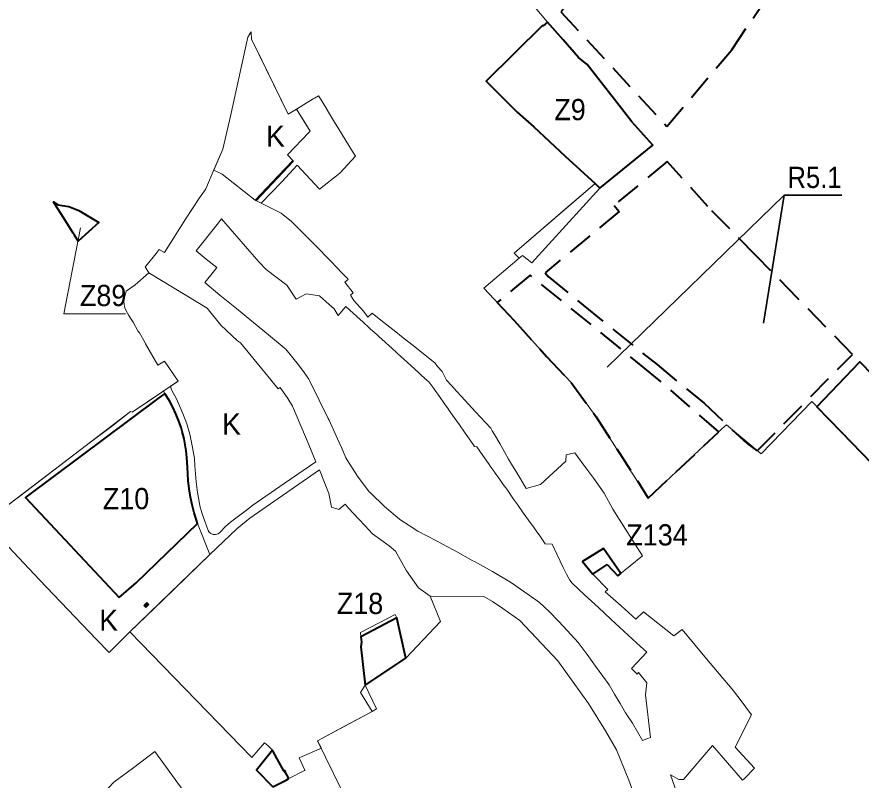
# Model space of a CAD drawing. Extents: x -650276 to -642489, y -1074425 to -1066658.
# Drawn here: x -646722 to -645767, y -1072612 to -1071749 of the extents above; entities that cross this region are included whole.
import ezdxf

# ---------------------------------------------------------------- set-up
doc = ezdxf.new("R2010")
doc.units = 0
doc.header["$LTSCALE"] = 9.6
doc.linetypes.add('MEDIUM_DASHED', pattern=[4.5, 3, -1.5])
for name, color, linetype, lineweight in [('1', 7, 'Continuous', 13), ('4', 7, 'Continuous', 40), ('43', 7, 'Continuous', 13), ('44', 7, 'Continuous', 40), ('45', 7, 'Continuous', 40), ('46', 7, 'Continuous', 13), ('47', 7, 'Continuous', 13), ('61', 7, 'MEDIUM_DASHED', 40), ('62', 7, 'Continuous', 35)]:
    doc.layers.add(name, color=color, linetype=linetype, lineweight=lineweight)

msp = doc.modelspace()

# ---------------------------------------------------------------- hatches: boundary and pattern name
at = {"layer": '1'}
msp.add_hatch(color=256, dxfattribs=at).paths.add_polyline_path([(-646578.73, -1072414.85), (-646576.66, -1072416.99), (-646573.22, -1072413.66), (-646575.31, -1072411.52)])

# ---------------------------------------------------------------- linework, layer by layer
for points in [[(-646154, -1072022), (-646160, -1072016), (-646156.858, -1072013.393), (-646068.317, -1071937.555), (-646102.04, -1071906.4), (-646137.74, -1071873.31), (-646156.59, -1071856.53), (-646174.69, -1071838.69), (-646191.57, -1071821.44), (-646136.12, -1071767.07), (-646127.84, -1071758.53), (-646127.12, -1071759.15), (-646122.16, -1071754.78), (-646136.17, -1071738.31)], [(-646565.01, -1072016.41), (-646561.43, -1072012.01), (-646555.52, -1072015.55), (-646531.63, -1071977.65), (-646515.67, -1071953.6), (-646510.36, -1071945.61), (-646508.83, -1071943.3), (-646498.33, -1071919.22), (-646489.34, -1071898.61), (-646480.81, -1071861.18), (-646461.09, -1071771.76), (-646459.66, -1071769.15), (-646457.52, -1071765.98), (-646456.96, -1071774.2), (-646415.46, -1071859.05), (-646405.99, -1071853.26), (-646387.17, -1071841.76), (-646385.73, -1071840.88), (-646381.21, -1071838.12), (-646378.15, -1071842.85), (-646363.05, -1071867.91), (-646358.29, -1071875.79), (-646342.76, -1071901.21), (-646339.33, -1071906.58), (-646357.09, -1071925.59), (-646380.09, -1071943.87), (-646405.32, -1071916.59), (-646422.82, -1071935.5), (-646446.22, -1071959.67), (-646423.62, -1071970.84), (-646411.66, -1071980.54), (-646397.04, -1071994.94), (-646382.64, -1072009.55), (-646369.88, -1072022.49), (-646367.74, -1072024.72), (-646360.53, -1072032.22), (-646354.71, -1072038.28), (-646348.89, -1072044.34), (-646347.47, -1072045.83), (-646349.03, -1072047.09), (-646351.45, -1072049.03), (-646342.13, -1072060.94), (-646344.94, -1072063.53), (-646341.21, -1072069.74), (-646337.87, -1072073.42), (-646330.33, -1072081.74), (-646325.21, -1072088.45), (-646320.51, -1072084.13), (-646312.51, -1072090.43), (-646307.16, -1072094.67), (-646300.49, -1072099.96), (-646293.83, -1072105.24), (-646287.16, -1072110.52), (-646272.37, -1072122.25), (-646249.36, -1072140.5), (-646246.39, -1072144.56), (-646241.37, -1072150.02), (-646236.35, -1072159.85), (-646230.66, -1072166.02), (-646224.96, -1072172.2), (-646219.27, -1072178.37), (-646211.37, -1072186.94), (-646203.48, -1072195.51), (-646197.78, -1072201.68), (-646192.09, -1072207.86), (-646186.39, -1072214.03), (-646184.57, -1072217.04), (-646182.05, -1072221.45), (-646176.21, -1072231.64), (-646170.37, -1072241.84), (-646166.08, -1072249.31), (-646161.69, -1072256.68), (-646157.3, -1072264.05), (-646152.81, -1072271.52), (-646148.45, -1072278.73), (-646146.27, -1072282.34), (-646130.2, -1072277.79), (-646101.53, -1072251.45), (-646101.18, -1072244.23), (-646091.27, -1072242.07), (-646081.08, -1072256.01), (-646069.73, -1072270.99), (-646057.93, -1072287.58), (-646048.32, -1072305.81), (-646026.55, -1072339.67), (-646014.64, -1072358.74), (-646042.65, -1072381.23), (-646054.43, -1072368.34), (-646071, -1072379.27), (-646053.82, -1072396.53), (-646056.71, -1072399.15), (-646038.76, -1072415.27), (-646022.31, -1072430.03), (-646013.49, -1072421.84)], [(-646381.21, -1071838.12), (-646385.73, -1071840.88), (-646387.17, -1071841.76), (-646405.99, -1071853.26), (-646399.72, -1071863.5)], [(-646380.09, -1071943.87), (-646357.09, -1071925.59), (-646339.33, -1071906.58), (-646342.76, -1071901.21), (-646358.29, -1071875.79), (-646363.05, -1071867.91), (-646378.15, -1071842.85), (-646381.21, -1071838.12)], [(-646399.72, -1071863.5), (-646390.732, -1071878.171), (-646391.83, -1071879.32), (-646416.2, -1071904.81), (-646410.25, -1071911.25), (-646426.84, -1071928.72), (-646453.04, -1071956.3), (-646446.22, -1071959.67)], [(-646446.22, -1071959.67), (-646422.82, -1071935.5), (-646405.32, -1071916.59), (-646380.09, -1071943.87)], [(-646068.317, -1071937.555), (-646099.073, -1071963.899), (-646156.858, -1072013.393)], [(-646154, -1072022), (-646150.226, -1072018.826), (-646139.98, -1072027.22), (-646062.91, -1071942.55), (-646068.317, -1071937.555)], [(-646009.81, -1072467.72), (-646021.04, -1072457.32), (-646035.81, -1072443.64), (-646050.33, -1072430.19), (-646064.38, -1072417.18), (-646080.11, -1072402.61), (-646094.3, -1072389.47), (-646096.74, -1072386.1), (-646100.79, -1072379.38), (-646104.34, -1072371.88), (-646111.23, -1072357.28), (-646116.89, -1072345.3), (-646124.57, -1072345.05), (-646130.92, -1072336.06), (-646135.06, -1072330.21), (-646137.35, -1072326.93), (-646143.44, -1072318.35), (-646149.48, -1072309.81), (-646156.16, -1072300.36), (-646160.44, -1072294.29), (-646162.83, -1072290.91), (-646167.16, -1072284.79), (-646169.4, -1072281.62), (-646172.17, -1072277.7), (-646175.95, -1072272.36), (-646177.05, -1072270.8), (-646181.94, -1072263.89), (-646182.5, -1072263.09), (-646186.83, -1072256.95), (-646188.78, -1072254.2), (-646193.5, -1072247.52), (-646195.15, -1072245.18), (-646202.08, -1072235.38), (-646204.52, -1072235.01), (-646210.34, -1072226.72), (-646216.04, -1072218.6), (-646221.81, -1072210.37), (-646227.62, -1072202.1), (-646233.19, -1072194.16), (-646234.49, -1072192.31), (-646238.48, -1072186.62), (-646239.32, -1072185.42), (-646243.62, -1072179.29), (-646244.21, -1072178.45), (-646249.07, -1072171.52), (-646250.54, -1072169.43), (-646253.99, -1072164.89), (-646256.42, -1072161.7), (-646258.35, -1072160.04), (-646264.53, -1072154.43), (-646267.64, -1072151.6), (-646276.92, -1072143.18), (-646284.31, -1072136.47), (-646291.65, -1072129.81), (-646299.17, -1072122.98), (-646300.37, -1072121.89), (-646306.22, -1072116.58), (-646312.43, -1072110.94), (-646313.68, -1072109.81), (-646318.69, -1072105.26), (-646321.85, -1072102.39), (-646324.94, -1072099.59), (-646329.95, -1072095.03), (-646331.17, -1072093.93), (-646337.42, -1072088.25), (-646338.2, -1072087.54), (-646345.68, -1072080.75), (-646350.2, -1072076.65), (-646358.85, -1072086.64), (-646363.59, -1072079.32), (-646369.14, -1072074.36), (-646380.25, -1072064.44), (-646395.21, -1072062.3), (-646406.46, -1072068.39), (-646417.04, -1072052.27), (-646440.49, -1072034.75), (-646448.23, -1072026.42), (-646458.91, -1072014.27), (-646490.776, -1071977.349), (-646495.86, -1071983.75), (-646519.64, -1072013.69)], [(-646595.86, -1072086.82), (-646598.67, -1072081.55), (-646600.22, -1072077.86), (-646600.8, -1072075.94), (-646601.16, -1072074.07), (-646601.42, -1072071.01), (-646601, -1072067.55), (-646599.86, -1072063.71), (-646598.827, -1072059.244), (-646588.75, -1072052.06), (-646573.05, -1072038.46), (-646577.31, -1072031.53), (-646576.72, -1072030.81), (-646565.01, -1072016.41)], [(-646519.64, -1072013.69), (-646508.3, -1072022.8), (-646496.18, -1072032.53), (-646502.89, -1072040.91), (-646509.76, -1072049.5), (-646492.67, -1072063.57), (-646490.82, -1072065.09), (-646473.97, -1072078.95), (-646456.63, -1072093.22), (-646454.82, -1072094.71), (-646437.75, -1072108.75), (-646420.06, -1072123.31), (-646418.13, -1072124.9), (-646403.75, -1072142.38), (-646397.31, -1072151.31), (-646392.06, -1072158.59), (-646391.02, -1072161.06), (-646380.5, -1072182.54), (-646370.34, -1072203.29), (-646369.17, -1072205.2), (-646359.65, -1072226.35), (-646354.89, -1072236.93), (-646350.13, -1072247.52), (-646349.03, -1072249.42), (-646337.06, -1072268.4)], [(-646156.858, -1072013.393), (-646160, -1072016), (-646154, -1072022)], [(-646008.07, -1072293.223), (-646067.08, -1072201.18), (-646095.44, -1072162.47), (-646123.06, -1072133.18), (-646159.66, -1072092.31), (-646194.191, -1072055.797), (-646154, -1072022)], [(-646577.08, -1072118.7), (-646577.41, -1072117.76), (-646583.9, -1072106.42), (-646585.08, -1072104.81), (-646591.02, -1072094.4), (-646593.13, -1072091.01), (-646595.86, -1072086.82)], [(-646737.449, -1072305.019), (-646643.55, -1072233.5), (-646593.85, -1072195.48), (-646592.2, -1072196.17), (-646539.94, -1072160.83), (-646555.49, -1072138.17), (-646563.11, -1072143.03), (-646577.08, -1072118.7)], [(-645674, -1072338), (-645823, -1072184), (-645880.412, -1072243.358), (-645919.698, -1072210.262), (-645924.734, -1072214.99), (-646008.065, -1072293.22)], [(-646293.93, -1072353.28), (-646301.43, -1072347.28), (-646320.28, -1072333.64), (-646328.57, -1072324.62), (-646335.52, -1072317.05), (-646347.2, -1072304.53), (-646351.15, -1072300), (-646358.28, -1072306.16), (-646366.62, -1072303.53), (-646369.35, -1072287.95), (-646380.12, -1072261.44), (-646459.03, -1072316.137), (-646473.069, -1072327.765), (-646504.244, -1072357.026), (-646557.188, -1072408.65), (-646594.561, -1072444.38), (-646456.592, -1072586.826)], [(-646337.06, -1072268.4), (-646323.76, -1072286.05), (-646322.37, -1072287.43), (-646306.56, -1072302.91), (-646289.72, -1072317.17), (-646287.88, -1072318.32), (-646278.46, -1072324.39), (-646268.81, -1072330.59), (-646248.36, -1072341.06), (-646246.79, -1072341.94), (-646236.62, -1072347.54), (-646226.6, -1072353.06), (-646206.45, -1072364.17), (-646204.61, -1072365.07), (-646184.28, -1072376.27), (-646164.58, -1072387.87), (-646162.91, -1072388.99), (-646152.72, -1072396.2), (-646142.81, -1072403.2), (-646131.25, -1072411.38), (-646120.15, -1072421.49), (-646109.85, -1072432.52), (-646099.59, -1072443.5), (-646087.36, -1072456.59), (-646077.32, -1072470.36), (-646067.89, -1072483.29), (-646059.6, -1072494.67), (-646052.46, -1072504.47), (-646046.19, -1072515.07), (-646040.06, -1072525.44), (-646033.79, -1072536.03), (-646025.88, -1072547.72), (-646014.58, -1072567.38), (-646009.73, -1072565.6), (-646005.7, -1072564.121), (-646011.28, -1072515.68), (-646009.61, -1072502.32), (-646018.97, -1072490.66), (-646020.51, -1072492.32), (-646027.04, -1072485.99), (-646009.81, -1072467.72)], [(-646433.36, -1072578.45), (-646432.57, -1072579.75), (-646427.95, -1072588.07), (-646420.36, -1072601.78), (-646419.02, -1072604.18), (-646419.47, -1072601.31), (-646419.11, -1072602.03), (-646414.77, -1072610.61), (-646397.18, -1072601.51), (-646396.49, -1072601.15), (-646403.01, -1072587.22), (-646402.24, -1072586.89), (-646377.84, -1072576.29), (-646382.41, -1072568.01), (-646320.62, -1072534.6), (-646333.56, -1072513.13), (-646328.45, -1072504.81), (-646333.34, -1072461.67), (-646332.68, -1072456.19), (-646333.33, -1072450.12), (-646333.84, -1072445.32), (-646332.82, -1072444.79), (-646294.51, -1072424.9), (-646292.44, -1072428.89), (-646282.47, -1072474.34), (-646243.17, -1072432.88), (-646254.75, -1072404.25), (-646268.05, -1072394.66), (-646281.83, -1072375.54), (-646293.93, -1072353.28)], [(-646013.49, -1072421.84), (-645979.11, -1072449.23), (-645969.88, -1072441.74), (-645955.1, -1072459.76), (-645944.25, -1072472.98), (-645927.82, -1072492.14)], [(-645927.82, -1072492.14), (-645913.04, -1072509.37), (-645904.25, -1072521.2), (-645891.33, -1072538.6), (-645909.952, -1072574.829), (-645888.07, -1072598.68), (-645899.69, -1072610.7), (-645901.33, -1072612.4), (-645935.38, -1072573), (-645968.24, -1072611.54), (-645973.45, -1072611.73), (-645982.84, -1072606.46), (-645955.51, -1072684.762)], [(-646456.592, -1072586.826), (-646442.31, -1072569.97), (-646438.05, -1072573.49), (-646433.36, -1072578.45)], [(-646524.818, -1072657.852), (-646517.19, -1072650.7), (-646511.84, -1072645.84), (-646510.28, -1072644.42), (-646531.13, -1072626.73), (-646534.36, -1072624), (-646566.49, -1072579.96), (-646591.49, -1072599.19), (-646612.66, -1072614.57), (-646618.94, -1072620.88), (-646629.86, -1072632.07), (-646627.32, -1072636.95), (-646605.23, -1072679.37), (-646589.37, -1072709.83)]]:
    msp.add_lwpolyline(points, dxfattribs=at)
msp.add_lwpolyline([(-646578.73, -1072414.85), (-646576.66, -1072416.99), (-646573.22, -1072413.66), (-646575.31, -1072411.52)], close=True, dxfattribs=at)
at = {"layer": '4'}
for points in [[(-646039.16, -1072378.43), (-646058.64, -1072350.29), (-646082.55, -1072364.84), (-646071, -1072379.27), (-646054.43, -1072368.34)], [(-646054.43, -1072368.34), (-646042.65, -1072381.23), (-646039.16, -1072378.43)]]:
    msp.add_lwpolyline(points, dxfattribs=at)
at = {"layer": '44'}
msp.add_lwpolyline([(-646652.18, -1071967.73), (-646629.655, -1071981.343), (-646653.198, -1072002.544), (-646657.32, -1071995.98), (-646658.79, -1071993.62), (-646669.31, -1071976.77), (-646676.79, -1071964.97), (-646681.07, -1071958.16), (-646675.99, -1071961.64), (-646663.87, -1071963.26)], close=True, dxfattribs=at)
at = {"layer": '44', "lineweight": 13}
msp.add_lwpolyline([(-646599.686, -1072084.891), (-646669.193, -1072084.891), (-646650.508, -1071987.658)], dxfattribs=at)
msp.add_lwpolyline([(-646599.686, -1072084.891), (-646669.193, -1072084.891), (-646650.508, -1071987.658)], dxfattribs=at)
at = {"layer": '45'}
msp.add_line((-646417.787, -1072612.168), (-646414.77, -1072610.61), dxfattribs=at)
for points in [[(-646102.04, -1071906.4), (-646068.317, -1071937.555), (-646062.91, -1071942.55), (-646002.93, -1071893.984), (-646026.64, -1071867.44), (-646043.49, -1071845.87), (-646077.32, -1071802.59), (-646087, -1071795), (-646104.5, -1071774.86), (-646122.16, -1071754.78), (-646127.12, -1071759.15), (-646127.84, -1071758.53), (-646191.57, -1071821.44), (-646174.69, -1071838.69), (-646156.59, -1071856.53), (-646137.74, -1071873.31)], [(-645817.219, -1072189.975), (-645768.649, -1072139.283), (-645740.45, -1072168.23), (-645559.34, -1072354.42), (-645546.82, -1072365.72), (-645550.41, -1072368.47), (-645636.37, -1072379.57), (-645650.78, -1072342.73), (-645674, -1072338), (-645789.298, -1072218.833)], [(-646606.848, -1072405.785), (-646587.666, -1072389.082), (-646518.208, -1072321.92), (-646519.417, -1072318.408), (-646522.007, -1072309.932), (-646524.282, -1072300.849), (-646526, -1072292.201), (-646527.5, -1072282.657), (-646528.566, -1072273.308), (-646529.182, -1072265.941), (-646529.607, -1072258.124), (-646530.188, -1072247.442), (-646530.892, -1072239.747), (-646531.93, -1072232.861), (-646533.286, -1072226.031), (-646535.344, -1072217.844), (-646536.772, -1072213.218), (-646539.168, -1072206.122), (-646539.168, -1072206.122), (-646542.484, -1072197.985), (-646546.09, -1072190.428), (-646549.793, -1072183.38), (-646554.56, -1072175.629), (-646555.051, -1072174.933), (-646563.299, -1072181.091), (-646710.684, -1072291.133), (-646712.634, -1072292.59)], [(-646333.34, -1072461.67), (-646328.45, -1072504.81), (-646282.47, -1072474.34), (-646292.44, -1072428.89), (-646333.33, -1072450.12), (-646332.68, -1072456.19)], [(-646333.34, -1072461.67), (-646328.45, -1072504.81), (-646282.47, -1072474.34), (-646292.44, -1072428.89), (-646333.33, -1072450.12), (-646332.68, -1072456.19)]]:
    msp.add_lwpolyline(points, close=True, dxfattribs=at)
for points in [[(-646420.36, -1072601.78), (-646427.95, -1072588.07), (-646432.57, -1072579.75), (-646433.36, -1072578.45), (-646451.458, -1072601.008), (-646433.024, -1072620.04), (-646417.787, -1072612.168)], [(-646414.77, -1072610.61), (-646419.11, -1072602.03), (-646419.47, -1072601.31), (-646419.02, -1072604.18), (-646420.36, -1072601.78)]]:
    msp.add_lwpolyline(points, dxfattribs=at)
at = {"layer": '47'}
msp.add_line((-646490.111, -1071926.754), (-646453.04, -1071956.3), dxfattribs=at)
for points in [[(-646453.04, -1071956.3), (-646451.87, -1071956.88), (-646409.4, -1071912.17), (-646416.2, -1071904.81), (-646391.83, -1071879.32), (-646390.732, -1071878.171), (-646405.99, -1071853.26), (-646415.46, -1071859.05), (-646445.115, -1071798.418), (-646456.96, -1071774.2), (-646457.52, -1071765.98), (-646461.09, -1071771.76), (-646480.81, -1071861.18), (-646489.34, -1071898.61), (-646499.741, -1071922.455), (-646490.111, -1071926.754)], [(-646507.28, -1072078.4), (-646530.073, -1072064.559), (-646573.05, -1072038.46), (-646588.75, -1072052.06), (-646598.827, -1072059.244), (-646599.86, -1072063.71), (-646601, -1072067.55), (-646601.42, -1072071.01), (-646601.16, -1072074.07), (-646600.8, -1072075.94), (-646600.22, -1072077.86), (-646598.67, -1072081.55), (-646595.86, -1072086.82), (-646593.13, -1072091.01), (-646591.02, -1072094.4), (-646585.08, -1072104.81), (-646583.9, -1072106.42), (-646577.41, -1072117.76), (-646577.08, -1072118.7), (-646563.11, -1072143.03), (-646555.49, -1072138.17), (-646539.94, -1072160.83), (-646548.676, -1072166.737)], [(-646472.72, -1072115.38), (-646491.69, -1072097.45), (-646507.28, -1072078.4)], [(-646426.98, -1072169.74), (-646441.961, -1072151.281), (-646469.41, -1072117.44), (-646472.72, -1072115.38)], [(-646548.676, -1072166.737), (-646547.606, -1072170.835), (-646541.822, -1072181.102), (-646534.527, -1072197.411), (-646530.167, -1072209.31), (-646526.798, -1072221.011), (-646523.628, -1072235.883)], [(-646415.84, -1072180.43), (-646424.56, -1072167.96), (-646426.98, -1072169.74)], [(-646731.82, -1072348.2), (-646696.83, -1072385.81), (-646632.356, -1072453.247), (-646618.158, -1072468.098), (-646611.091, -1072460.994), (-646594.606, -1072444.422), (-646594.561, -1072444.38), (-646504.244, -1072357.026), (-646518.208, -1072321.92), (-646587.666, -1072389.082), (-646606.848, -1072405.785), (-646712.634, -1072292.59), (-646563.299, -1072181.091), (-646556.591, -1072176.083), (-646555.051, -1072174.933), (-646556.693, -1072172.16), (-646568.051, -1072179.84), (-646592.2, -1072196.17), (-646593.85, -1072195.48), (-646614.075, -1072210.952), (-646643.55, -1072233.5), (-646693.58, -1072271.606), (-646716.167, -1072288.809), (-646737.449, -1072305.019)], [(-646391.77, -1072233.91), (-646410.68, -1072189.36), (-646415.84, -1072180.43)], [(-646523.628, -1072235.883), (-646523.628, -1072235.883), (-646521.646, -1072248.378), (-646521.051, -1072256.707), (-646519.756, -1072274.861), (-646518.079, -1072287.051), (-646516.692, -1072294.983), (-646515.305, -1072301.925), (-646512.729, -1072311.048), (-646509.954, -1072319.377), (-646506.189, -1072329.889), (-646504.802, -1072331.971), (-646503.018, -1072333.459), (-646500.244, -1072334.45), (-646497.569, -1072334.55), (-646494.794, -1072333.558), (-646492.813, -1072332.07), (-646486.273, -1072325.526), (-646480.923, -1072320.667), (-646462.79, -1072306.784), (-646455.557, -1072301.131), (-646420.085, -1072276.737), (-646384.056, -1072252.138), (-646391.77, -1072233.91)], [(-645999.622, -1072714.927), (-646006.66, -1072681.4), (-646019.16, -1072642.35), (-646030.17, -1072612.31), (-646043.87, -1072578.12), (-646056.42, -1072556.49), (-646075.82, -1072525.54), (-646110.61, -1072477.49), (-646153.49, -1072431.54), (-646172.81, -1072418.2), (-646184.449, -1072410.256), (-646194.19, -1072404.62), (-646254.75, -1072404.25), (-646243.17, -1072432.88), (-646282.47, -1072474.34), (-646328.45, -1072504.81), (-646315.452, -1072531.573)], [(-646315.452, -1072531.573), (-646320.62, -1072534.6), (-646350.18, -1072550.59), (-646382.41, -1072568.01), (-646345.6, -1072642.55), (-646368.51, -1072652.81), (-646371.66, -1072654.2), (-646342.08, -1072717.43), (-646367.72, -1072730.68), (-646321.171, -1072780.535), (-646292.17, -1072811.6), (-646261.97, -1072849.66), (-646255.39, -1072850.83), (-646249.04, -1072847.16), (-646253.56, -1072838.8), (-646288.27, -1072810.22), (-646199.72, -1072763.1), (-646194.296, -1072760.193)]]:
    msp.add_lwpolyline(points, dxfattribs=at)
at = {"layer": '61'}
for points in [[(-645909.13, -1071478.56), (-645989, -1071611), (-646107, -1071743), (-645987.026, -1071872.902), (-645913.616, -1071786.041), (-645835.644, -1071670.191), (-645768.62, -1071540.17)], [(-645896.15, -1072231.57), (-645884.949, -1072239.96), (-645777.057, -1072130.664), (-645839.31, -1072066.947), (-645885.655, -1072019.486), (-645940.8, -1071963.54), (-645986.568, -1071912.301), (-646046.78, -1071962.265), (-646041.113, -1071969.094), (-646124.568, -1072038.344), (-646121.403, -1072042.471), (-646081.78, -1072075), (-645998.22, -1072142.19), (-645945, -1072186)], [(-646141.703, -1072041.072), (-646178.915, -1072071.95), (-646159.66, -1072092.31), (-646123.06, -1072133.18), (-646095.44, -1072162.47), (-646067.08, -1072201.18), (-646008.065, -1072293.22), (-645928.101, -1072218.151), (-646005.793, -1072151.499)]]:
    msp.add_lwpolyline(points, close=True, dxfattribs=at)
at = {"layer": '62'}
msp.add_line((-645854.421, -1071950.737), (-645877.767, -1072095.485), dxfattribs=at)
msp.add_lwpolyline([(-645789.051, -1071950.737), (-645854.421, -1071950.737), (-646054.422, -1072145.291)], dxfattribs=at)

# ---------------------------------------------------------------- texts
at = {"layer": '4', "width": 0.95}
msp.add_text('Z134', height=24, dxfattribs=at).set_placement((-646032.947, -1072346.856))
at = {"layer": '43'}
for p in [(-646440.579, -1071895.779), (-646490.42, -1072221.403), (-646629.338, -1072443.411)]:
    msp.add_text('K', height=24, dxfattribs=at).set_placement(p)
at = {"layer": '44', "width": 0.95}
msp.add_text('Z89', height=24, dxfattribs=at).set_placement((-646651.144, -1072076.059))
msp.add_text('Z89', height=24, dxfattribs=at).set_placement((-646651.144, -1072076.059))
at = {"layer": '46', "width": 0.95}
for s, p in [('Z9', (-646114.385, -1071865.725)), ('Z10', (-646625.207, -1072305.81)), ('Z18', (-646360.479, -1072424.402))]:
    msp.add_text(s, height=24, dxfattribs=at).set_placement(p)
at = {"layer": '62', "width": 0.9}
msp.add_text('R5.1', height=24, dxfattribs=at).set_placement((-645850.499, -1071942.459))

doc.saveas('drawing.dxf')
